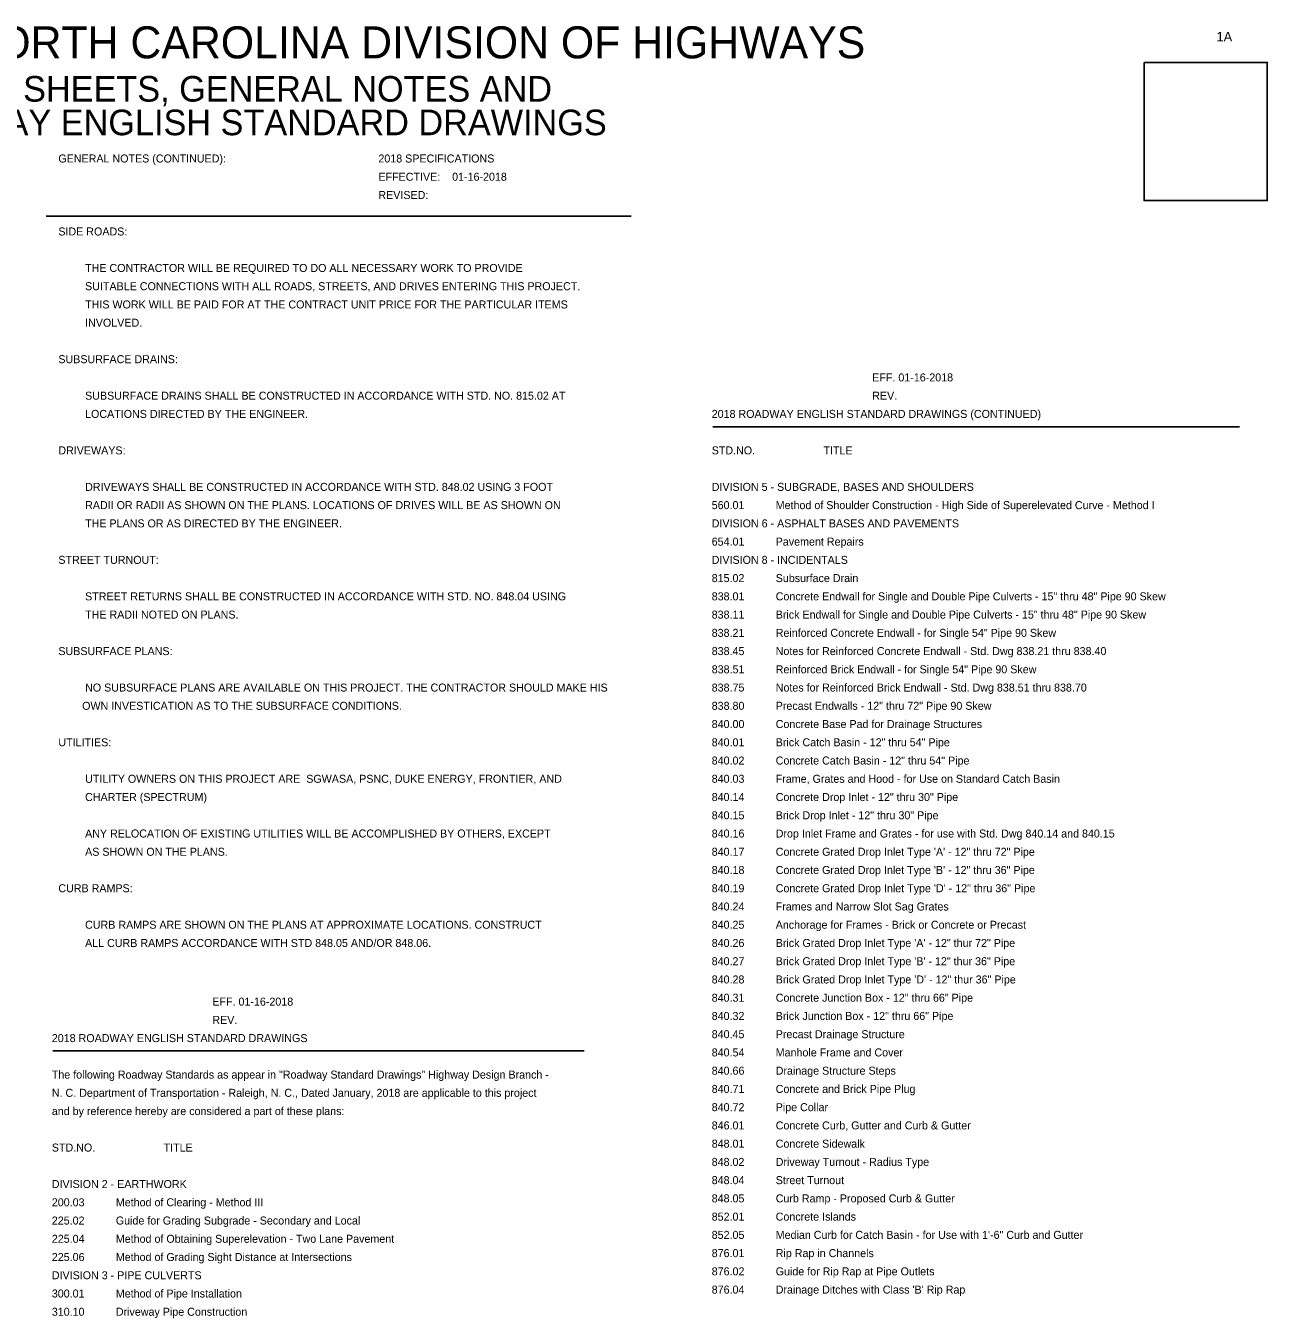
# Model space of a CAD drawing. Extents: x 573079.6 to 573111.5, y -55220.2 to -55200.
# Drawn here: x 573092.07 to 573111.46, y -55220.19 to -55200 of the extents above; entities that cross this region are included whole.
import ezdxf

# ---------------------------------------------------------------- set-up
doc = ezdxf.new("R2010")
doc.units = 0
for name, color, linetype in [('Default', 7, 'Continuous'), ('Scratch_Level_4', 7, 'Continuous'), ('Sheet Data Field CELL', 7, 'Continuous'), ('Sheet Data Text CELL', 7, 'Continuous'), ('Sheet Title CELL', 7, 'Continuous')]:
    doc.layers.add(name, color=color, linetype=linetype)

msp = doc.modelspace()

# ---------------------------------------------------------------- linework, layer by layer
at = {"layer": 'Scratch_Level_4'}
msp.add_lwpolyline([(573109.539, -55200.571), (573111.462, -55200.571), (573111.462, -55202.73), (573109.539, -55202.73)], close=True, dxfattribs=at)
at = {"layer": 'Sheet Data Text CELL'}
for p, q in [((573092.388, -55202.973), (573101.526, -55202.973)), ((573102.8, -55206.265), (573111.031, -55206.265)), ((573092.491, -55216.015), (573100.79, -55216.015))]:
    msp.add_line(p, q, dxfattribs=at)

# ---------------------------------------------------------------- texts
at = {"layer": 'Default'}
for s, p in [('GENERAL NOTES (CONTINUED):                         ', (573092.577, -55202.135)), ('2018 SPECIFICATIONS', (573097.577, -55202.135)), ('EFFECTIVE:    01-16-2018', (573097.577, -55202.42)), ('REVISED:  ', (573097.577, -55202.705)), ('SIDE ROADS:  ', (573092.577, -55203.275)), ('         THE CONTRACTOR WILL BE REQUIRED TO DO ALL NECESSARY WORK TO PROVIDE ', (573092.577, -55203.845)), ('         SUITABLE CONNECTIONS WITH ALL ROADS, STREETS, AND DRIVES ENTERING THIS PROJECT.  ', (573092.577, -55204.13)), ('         THIS WORK WILL BE PAID FOR AT THE CONTRACT UNIT PRICE FOR THE PARTICULAR ITEMS ', (573092.577, -55204.415)), ('         INVOLVED.  ', (573092.577, -55204.7)), ('SUBSURFACE DRAINS:', (573092.577, -55205.27)), ('         SUBSURFACE DRAINS SHALL BE CONSTRUCTED IN ACCORDANCE WITH STD. NO. 815.02 AT', (573092.577, -55205.84)), ('         LOCATIONS DIRECTED BY THE ENGINEER.', (573092.577, -55206.125)), ('DRIVEWAYS:', (573092.577, -55206.695)), ('         DRIVEWAYS SHALL BE CONSTRUCTED IN ACCORDANCE WITH STD. 848.02 USING 3 FOOT', (573092.577, -55207.265)), ('         RADII OR RADII AS SHOWN ON THE PLANS. LOCATIONS OF DRIVES WILL BE AS SHOWN ON', (573092.577, -55207.55)), ('         THE PLANS OR AS DIRECTED BY THE ENGINEER.', (573092.577, -55207.835)), ('STREET TURNOUT:', (573092.577, -55208.405)), ('         STREET RETURNS SHALL BE CONSTRUCTED IN ACCORDANCE WITH STD. NO. 848.04 USING', (573092.577, -55208.975)), ('         THE RADII NOTED ON PLANS.', (573092.577, -55209.26)), ('SUBSURFACE PLANS:', (573092.577, -55209.83)), ('         NO SUBSURFACE PLANS ARE AVAILABLE ON THIS PROJECT. THE CONTRACTOR SHOULD MAKE HIS  ', (573092.577, -55210.4)), ('        OWN INVESTICATION AS TO THE SUBSURFACE CONDITIONS.', (573092.577, -55210.685)), ('UTILITIES:  ', (573092.577, -55211.255)), ('         UTILITY OWNERS ON THIS PROJECT ARE  SGWASA, PSNC, DUKE ENERGY, FRONTIER, AND', (573092.577, -55211.825)), ('         CHARTER (SPECTRUM)', (573092.577, -55212.11)), ('         ANY RELOCATION OF EXISTING UTILITIES WILL BE ACCOMPLISHED BY OTHERS, EXCEPT', (573092.577, -55212.68)), ('         AS SHOWN ON THE PLANS.', (573092.577, -55212.965)), ('CURB RAMPS:', (573092.577, -55213.535)), ('         CURB RAMPS ARE SHOWN ON THE PLANS AT APPROXIMATE LOCATIONS. CONSTRUCT', (573092.577, -55214.105)), ('         ALL CURB RAMPS ACCORDANCE WITH STD 848.05 AND/OR 848.06.', (573092.577, -55214.39))]:
    msp.add_text(s, height=0.125, rotation=360, dxfattribs=at).set_placement(p)
at = {"layer": 'Sheet Data Field CELL'}
msp.add_text('1A', height=0.15, rotation=0, dxfattribs=at).set_placement((573110.67, -55200.244))
for s, p in [('INDEX OF SHEETS, GENERAL NOTES AND', (573089.352, -55201.184)), ('2018 ROADWAY ENGLISH STANDARD DRAWINGS', (573088.364, -55201.709))]:
    msp.add_text(s, height=0.4, dxfattribs=at).set_placement(p)
at = {"layer": 'Sheet Data Text CELL'}
for s, p in [('                                                      EFF. 01-16-2018', (573102.784, -55205.555)), ('                                                      REV. ', (573102.784, -55205.84)), ('2018 ROADWAY ENGLISH STANDARD DRAWINGS (CONTINUED)', (573102.784, -55206.125)), ('STD.NO.                       TITLE', (573102.784, -55206.695)), ('DIVISION 5 - SUBGRADE, BASES AND SHOULDERS', (573102.784, -55207.265)), ('560.01', (573102.784, -55207.55)), ('Method of Shoulder Construction - High Side of Superelevated Curve - Method I', (573103.784, -55207.55)), ('DIVISION 6 - ASPHALT BASES AND PAVEMENTS', (573102.784, -55207.835)), ('654.01', (573102.784, -55208.12)), ('Pavement Repairs', (573103.784, -55208.12)), ('DIVISION 8 - INCIDENTALS', (573102.784, -55208.405)), ('815.02', (573102.784, -55208.69)), ('Subsurface Drain', (573103.784, -55208.69)), ('838.01', (573102.784, -55208.975)), ('Concrete Endwall for Single and Double Pipe Culverts - 15" thru 48" Pipe 90 Skew', (573103.784, -55208.975)), ('838.11', (573102.784, -55209.26)), ('Brick Endwall for Single and Double Pipe Culverts - 15" thru 48" Pipe 90 Skew', (573103.784, -55209.26)), ('838.21', (573102.784, -55209.545)), ('Reinforced Concrete Endwall - for Single 54" Pipe 90 Skew', (573103.784, -55209.545)), ('838.45', (573102.784, -55209.83)), ('Notes for Reinforced Concrete Endwall - Std. Dwg 838.21 thru 838.40', (573103.784, -55209.83)), ('838.51', (573102.784, -55210.115)), ('Reinforced Brick Endwall - for Single 54" Pipe 90 Skew', (573103.784, -55210.115)), ('838.75', (573102.784, -55210.4)), ('Notes for Reinforced Brick Endwall - Std. Dwg 838.51 thru 838.70', (573103.784, -55210.4)), ('838.80', (573102.784, -55210.685)), ('Precast Endwalls - 12" thru 72" Pipe 90 Skew', (573103.784, -55210.685)), ('840.00', (573102.784, -55210.97)), ('Concrete Base Pad for Drainage Structures', (573103.784, -55210.97)), ('840.01', (573102.784, -55211.255)), ('Brick Catch Basin - 12" thru 54" Pipe', (573103.784, -55211.255)), ('840.02', (573102.784, -55211.54)), ('Concrete Catch Basin - 12" thru 54" Pipe', (573103.784, -55211.54)), ('840.03', (573102.784, -55211.825)), ('Frame, Grates and Hood - for Use on Standard Catch Basin', (573103.784, -55211.825)), ('840.14', (573102.784, -55212.11)), ('Concrete Drop Inlet - 12" thru 30" Pipe', (573103.784, -55212.11)), ('840.15', (573102.784, -55212.395)), ('Brick Drop Inlet - 12" thru 30" Pipe', (573103.784, -55212.395)), ('840.16', (573102.784, -55212.68)), ('Drop Inlet Frame and Grates - for use with Std. Dwg 840.14 and 840.15', (573103.784, -55212.68)), ('840.17', (573102.784, -55212.965)), ('Concrete Grated Drop Inlet Type \'A\' - 12" thru 72" Pipe', (573103.784, -55212.965)), ('840.18', (573102.784, -55213.25)), ('Concrete Grated Drop Inlet Type \'B\' - 12" thru 36" Pipe', (573103.784, -55213.25)), ('840.19', (573102.784, -55213.535)), ('Concrete Grated Drop Inlet Type \'D\' - 12" thru 36" Pipe', (573103.784, -55213.535)), ('840.24', (573102.784, -55213.82)), ('Frames and Narrow Slot Sag Grates', (573103.784, -55213.82)), ('840.25', (573102.784, -55214.105)), ('Anchorage for Frames - Brick or Concrete or Precast', (573103.784, -55214.105)), ('840.26', (573102.784, -55214.39)), ('Brick Grated Drop Inlet Type \'A\' - 12" thur 72" Pipe', (573103.784, -55214.39)), ('840.27', (573102.784, -55214.675)), ('Brick Grated Drop Inlet Type \'B\' - 12" thur 36" Pipe', (573103.784, -55214.675)), ('840.28', (573102.784, -55214.96)), ('Brick Grated Drop Inlet Type \'D\' - 12" thur 36" Pipe', (573103.784, -55214.96)), ('                                                      EFF. 01-16-2018', (573092.475, -55215.306)), ('840.31', (573102.784, -55215.245)), ('Concrete Junction Box - 12" thru 66" Pipe', (573103.784, -55215.245)), ('                                                      REV. ', (573092.475, -55215.591)), ('840.32', (573102.784, -55215.53)), ('Brick Junction Box - 12" thru 66" Pipe', (573103.784, -55215.53)), ('2018 ROADWAY ENGLISH STANDARD DRAWINGS', (573092.475, -55215.876)), ('840.45', (573102.784, -55215.815)), ('Precast Drainage Structure', (573103.784, -55215.815)), ('840.54', (573102.784, -55216.1)), ('Manhole Frame and Cover', (573103.784, -55216.1)), ('840.66', (573102.784, -55216.385)), ('Drainage Structure Steps', (573103.784, -55216.385)), ('The following Roadway Standards as appear in "Roadway Standard Drawings" Highway Design Branch -', (573092.475, -55216.446)), ('N. C. Department of Transportation - Raleigh, N. C., Dated January, 2018 are applicable to this project', (573092.475, -55216.731)), ('840.71', (573102.784, -55216.67)), ('Concrete and Brick Pipe Plug', (573103.784, -55216.67)), ('840.72', (573102.784, -55216.955)), ('Pipe Collar', (573103.784, -55216.955)), ('and by reference hereby are considered a part of these plans:', (573092.475, -55217.016)), ('846.01', (573102.784, -55217.24)), ('Concrete Curb, Gutter and Curb & Gutter', (573103.784, -55217.24)), ('STD.NO.                       TITLE', (573092.475, -55217.586)), ('848.01', (573102.784, -55217.525)), ('Concrete Sidewalk', (573103.784, -55217.525)), ('848.02', (573102.784, -55217.81)), ('Driveway Turnout - Radius Type', (573103.784, -55217.81)), ('DIVISION 2 - EARTHWORK', (573092.475, -55218.156)), ('848.04', (573102.784, -55218.095)), ('Street Turnout', (573103.784, -55218.095)), ('848.05', (573102.784, -55218.38)), ('Curb Ramp - Proposed Curb & Gutter', (573103.784, -55218.38)), ('200.03', (573092.475, -55218.441)), ('Method of Clearing - Method III', (573093.475, -55218.441)), ('225.02', (573092.475, -55218.726)), ('Guide for Grading Subgrade - Secondary and Local', (573093.475, -55218.726)), ('852.01', (573102.784, -55218.665)), ('Concrete Islands', (573103.784, -55218.665)), ('225.04', (573092.475, -55219.011)), ('Method of Obtaining Superelevation - Two Lane Pavement', (573093.475, -55219.011)), ('852.05', (573102.784, -55218.95)), ('Median Curb for Catch Basin - for Use with 1\'-6" Curb and Gutter', (573103.784, -55218.95)), ('225.06', (573092.475, -55219.296)), ('Method of Grading Sight Distance at Intersections', (573093.475, -55219.296)), ('876.01', (573102.784, -55219.235)), ('Rip Rap in Channels', (573103.784, -55219.235)), ('DIVISION 3 - PIPE CULVERTS', (573092.475, -55219.581)), ('876.02', (573102.784, -55219.52)), ('Guide for Rip Rap at Pipe Outlets', (573103.784, -55219.52)), ('876.04', (573102.784, -55219.805)), ("Drainage Ditches with Class 'B' Rip Rap", (573103.784, -55219.805)), ('300.01', (573092.475, -55219.866)), ('Method of Pipe Installation ', (573093.475, -55219.866)), ('310.10', (573092.475, -55220.151)), ('Driveway Pipe Construction', (573093.475, -55220.151))]:
    msp.add_text(s, height=0.125, dxfattribs=at).set_placement(p)
at = {"layer": 'Sheet Title CELL'}
msp.add_text('STATE OF NORTH CAROLINA DIVISION OF HIGHWAYS', height=0.5, dxfattribs=at).set_placement((573087.686, -55200.508))

doc.saveas('drawing.dxf')
